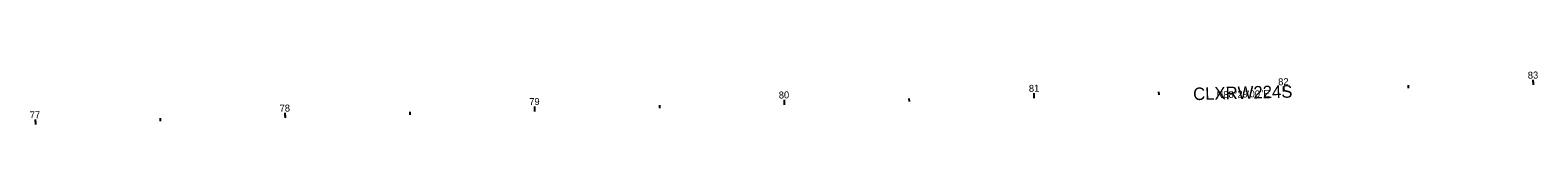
# Model space of a CAD drawing. Extents: x 2402033 to 2407435, y 498456 to 498900.
# Drawn here: x 2404732 to 2405335, y 498712 to 498733 of the extents above; entities that cross this region are included whole.
import ezdxf

# ---------------------------------------------------------------- set-up
doc = ezdxf.new("R2010")
doc.units = 0
for name, color, linetype in [('DR_P_Ditch', 7, 'Continuous'), ('DT_P_Graded_Shoulder', 7, 'Continuous'), ('MD_P_DNC', 7, 'Continuous'), ('MD_P_GRADE_BREAK', 7, 'Continuous'), ('RW_P_Esmt_CH', 7, 'Continuous'), ('RW_P_Esmt_TMP', 7, 'Continuous'), ('RW_X_CL_1000_Distances', 7, 'Continuous'), ('RW_X_Esmt_RR', 7, 'Continuous'), ('RW_X_Esmt_SH', 7, 'Continuous')]:
    doc.layers.add(name, color=color, linetype=linetype)

msp = doc.modelspace()

# ---------------------------------------------------------------- linework, layer by layer
at = {"layer": 'DR_P_Ditch'}
msp.add_line((2405033.76, 498719.55), (2405033.71, 498721.55), dxfattribs=at)
at = {"layer": 'RW_P_Esmt_CH'}
for p, q in [((2405233.69, 498724.84), (2405233.66, 498726.04)), ((2405333.66, 498727.49), (2405333.63, 498728.69)), ((2405033.76, 498719.55), (2405033.71, 498721.55)), ((2405133.73, 498722.19), (2405133.7, 498723.39)), ((2404733.87, 498711.61), (2404733.84, 498712.81)), ((2404833.83, 498714.25), (2404833.8, 498715.45)), ((2404933.8, 498716.9), (2404933.77, 498718.1))]:
    msp.add_line(p, q, dxfattribs=at)
at = {"layer": 'RW_X_Esmt_SH'}
for p, q in [((2405183.71, 498723.52), (2405183.68, 498724.72)), ((2405233.69, 498724.84), (2405233.64, 498726.84)), ((2405283.67, 498726.16), (2405283.64, 498727.36)), ((2405333.66, 498727.49), (2405333.6, 498729.49)), ((2404933.8, 498716.9), (2404933.74, 498718.9)), ((2404983.78, 498718.22), (2404983.75, 498719.42)), ((2405033.76, 498719.55), (2405033.71, 498721.55)), ((2405083.74, 498720.87), (2405083.71, 498722.07)), ((2405133.73, 498722.19), (2405133.67, 498724.19)), ((2404733.87, 498711.61), (2404733.81, 498713.61)), ((2404783.85, 498712.93), (2404783.82, 498714.13)), ((2404833.83, 498714.25), (2404833.78, 498716.25)), ((2404883.81, 498715.58), (2404883.78, 498716.78))]:
    msp.add_line(p, q, dxfattribs=at)

# ---------------------------------------------------------------- texts
at = {"layer": 'DR_P_Ditch'}
msp.add_text('80', height=2.8, rotation=1.5166, dxfattribs=at).set_placement((2405031.47, 498722.03))
at = {"layer": 'DT_P_Graded_Shoulder'}
msp.add_text('CLXRW224S', height=5, rotation=1.5166, dxfattribs=at).set_placement((2405197.44, 498721.38))
at = {"layer": 'MD_P_DNC'}
msp.add_text('CLXRW224S', height=5, rotation=1.5166, dxfattribs=at).set_placement((2405197.44, 498721.38))
at = {"layer": 'MD_P_GRADE_BREAK'}
msp.add_text('CLXRW224S', height=5, rotation=1.5166, dxfattribs=at).set_placement((2405197.44, 498721.38))
at = {"layer": 'RW_P_Esmt_CH'}
msp.add_text('80', height=2.8, rotation=1.5166, dxfattribs=at).set_placement((2405031.47, 498722.03))
at = {"layer": 'RW_P_Esmt_TMP'}
msp.add_text('N88°29\'00"E', height=2.8, rotation=1.5166, dxfattribs=at).set_placement((2405206.78, 498722.13))
at = {"layer": 'RW_X_CL_1000_Distances'}
msp.add_text('N88°29\'00"E', height=2.8, rotation=1.5166, dxfattribs=at).set_placement((2405206.78, 498722.13))
at = {"layer": 'RW_X_Esmt_RR'}
msp.add_text('N88°29\'00"E', height=2.8, rotation=1.5166, dxfattribs=at).set_placement((2405206.78, 498722.13))
at = {"layer": 'RW_X_Esmt_SH'}
for s, p in [('83', (2405331.44, 498729.97)), ('80', (2405031.47, 498722.03)), ('81', (2405131.63, 498724.68)), ('82', (2405231.46, 498727.32)), ('78', (2404831.55, 498716.74)), ('79', (2404931.53, 498719.38)), ('77', (2404731.5, 498714.06))]:
    msp.add_text(s, height=2.8, rotation=1.5166, dxfattribs=at).set_placement(p)

doc.saveas('drawing.dxf')
